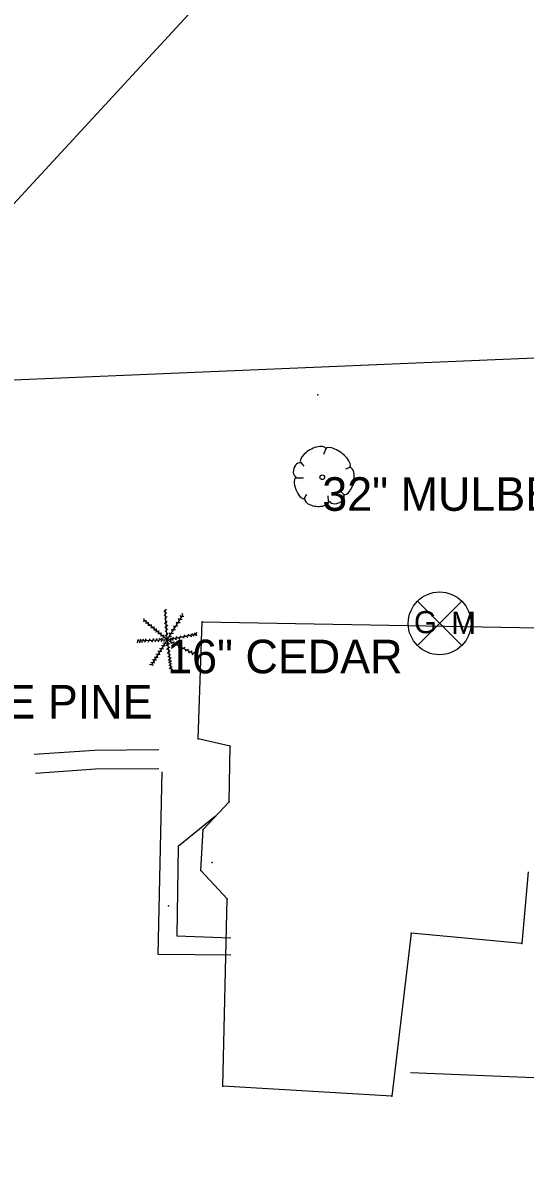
# Model space of a CAD drawing. Extents: x 1930288 to 1941089, y 588389 to 611475.
# Drawn here: x 1930694.7 to 1930769.5, y 598010.8 to 598182.1 of the extents above; entities that cross this region are included whole.
import ezdxf

# ---------------------------------------------------------------- set-up
doc = ezdxf.new("R2010")
doc.units = 0
for name, color, linetype in [('S_BUILDING', 7, 'Continuous'), ('S_DRIVEWAY', 7, 'Continuous'), ('S_GAS_UTILITIES', 7, 'Continuous'), ('S_MSC_PT_SYM', 7, 'Continuous'), ('S_SIDEWALK', 7, 'Continuous'), ('S_STR_PT_SYM', 7, 'Continuous'), ('S_TREE', 7, 'Continuous'), ('S_TREE_ANNOT', 7, 'Continuous'), ('S_UNDERGROUND_CABLE', 7, 'Continuous')]:
    doc.layers.add(name, color=color, linetype=linetype)

msp = doc.modelspace()

# ---------------------------------------------------------------- linework, layer by layer
at = {"layer": 'S_BUILDING'}
for p, q in [((1930720.81, 598075.51), (1930721.4, 598092.94)), ((1930721.4, 598092.94), (1930771.5, 598092.05)), ((1930725.6, 598074.42), (1930720.81, 598075.51)), ((1930725.42, 598066.11), (1930725.6, 598074.42)), ((1930721.59, 598061.99), (1930725.42, 598066.11)), ((1930721.23, 598055.87), (1930721.59, 598061.99)), ((1930725.15, 598051.69), (1930721.23, 598055.87)), ((1930769.97, 598055.71), (1930769.07, 598044.99)), ((1930724.49, 598023.76), (1930725.15, 598051.69)), ((1930752.57, 598046.55), (1930749.68, 598022.29)), ((1930769.07, 598044.99), (1930752.57, 598046.55)), ((1930749.68, 598022.29), (1930724.49, 598023.76))]:
    msp.add_line(p, q, dxfattribs=at)
at = {"layer": 'S_DRIVEWAY'}
msp.add_lwpolyline([(1930752.46, 598025.79), (1930772.06, 598025.01), (1930774.1, 598023.8), (1930774.87, 598021.62), (1930775.13, 598011.33), (1930788.72, 598010.83), (1930789.53, 598023.35), (1930791.28, 598024.6), (1930814.28, 598024.07), (1930827.31, 598023.8), (1930840.35, 598023.53), (1930845.84, 598023.33)], dxfattribs=at)
at = {"layer": 'S_GAS_UTILITIES'}
for p, q in [((1930763.56, 598231.34), (1930683.07, 598144.05)), ((1930753.49, 598089.39), (1930760.11, 598096.01)), ((1930753.49, 598096.01), (1930760.11, 598089.39))]:
    msp.add_line(p, q, dxfattribs=at)
msp.add_circle((1930756.8, 598092.7), 4.68, dxfattribs=at)
at = {"layer": 'S_MSC_PT_SYM'}
for points in [[(1930738.65, 598126.76), (1930738.65, 598126.81), (1930738.65, 598126.76), (1930738.6, 598126.76), (1930738.65, 598126.76), (1930738.65, 598126.71), (1930738.65, 598126.76), (1930738.7, 598126.76)], [(1930722.92, 598057.07), (1930722.92, 598057.12), (1930722.92, 598057.07), (1930722.86, 598057.07), (1930722.92, 598057.07), (1930722.92, 598057.02), (1930722.92, 598057.07), (1930722.97, 598057.07)], [(1930716.4, 598050.61), (1930716.4, 598050.66), (1930716.4, 598050.61), (1930716.35, 598050.61), (1930716.4, 598050.61), (1930716.4, 598050.56), (1930716.4, 598050.61), (1930716.45, 598050.61)]]:
    msp.add_lwpolyline(points, dxfattribs=at)
at = {"layer": 'S_SIDEWALK'}
for points in [[(1930696.38, 598073.19), (1930705.4, 598073.81), (1930714.96, 598073.9)], [(1930696.57, 598070.4), (1930705.51, 598071.01), (1930714.98, 598071.1)], [(1930725.69, 598043.3), (1930714.87, 598043.4), (1930715.16, 598056.98), (1930715.44, 598070.57)], [(1930723.42, 598063.97), (1930717.86, 598059.45), (1930717.66, 598046.16), (1930725.67, 598045.88)]]:
    msp.add_lwpolyline(points, dxfattribs=at)
at = {"layer": 'S_STR_PT_SYM'}
for points in [[(1930721.4, 598092.94), (1930721.4, 598092.99), (1930721.4, 598092.94), (1930721.35, 598092.94), (1930721.4, 598092.94), (1930721.4, 598092.89), (1930721.4, 598092.94), (1930721.45, 598092.94)], [(1930720.81, 598075.51), (1930720.81, 598075.56), (1930720.81, 598075.51), (1930720.76, 598075.51), (1930720.81, 598075.51), (1930720.81, 598075.46), (1930720.81, 598075.51), (1930720.86, 598075.51)], [(1930725.6, 598074.42), (1930725.6, 598074.47), (1930725.6, 598074.42), (1930725.55, 598074.42), (1930725.6, 598074.42), (1930725.6, 598074.37), (1930725.6, 598074.42), (1930725.65, 598074.42)], [(1930725.42, 598066.11), (1930725.42, 598066.16), (1930725.42, 598066.11), (1930725.37, 598066.11), (1930725.42, 598066.11), (1930725.42, 598066.06), (1930725.42, 598066.11), (1930725.47, 598066.11)], [(1930721.59, 598061.99), (1930721.59, 598062.04), (1930721.59, 598061.99), (1930721.54, 598061.99), (1930721.59, 598061.99), (1930721.59, 598061.94), (1930721.59, 598061.99), (1930721.64, 598061.99)], [(1930721.23, 598055.87), (1930721.23, 598055.92), (1930721.23, 598055.87), (1930721.18, 598055.87), (1930721.23, 598055.87), (1930721.23, 598055.82), (1930721.23, 598055.87), (1930721.28, 598055.87)], [(1930725.15, 598051.69), (1930725.15, 598051.74), (1930725.15, 598051.69), (1930725.1, 598051.69), (1930725.15, 598051.69), (1930725.15, 598051.64), (1930725.15, 598051.69), (1930725.2, 598051.69)], [(1930752.57, 598046.55), (1930752.57, 598046.6), (1930752.57, 598046.55), (1930752.52, 598046.55), (1930752.57, 598046.55), (1930752.57, 598046.5), (1930752.57, 598046.55), (1930752.62, 598046.55)], [(1930769.07, 598044.99), (1930769.07, 598045.04), (1930769.07, 598044.99), (1930769.02, 598044.99), (1930769.07, 598044.99), (1930769.07, 598044.94), (1930769.07, 598044.99), (1930769.12, 598044.99)], [(1930724.49, 598023.76), (1930724.49, 598023.81), (1930724.49, 598023.76), (1930724.44, 598023.76), (1930724.49, 598023.76), (1930724.49, 598023.71), (1930724.49, 598023.76), (1930724.54, 598023.76)], [(1930749.68, 598022.29), (1930749.68, 598022.34), (1930749.68, 598022.29), (1930749.63, 598022.29), (1930749.68, 598022.29), (1930749.68, 598022.24), (1930749.68, 598022.29), (1930749.73, 598022.29)]]:
    msp.add_lwpolyline(points, dxfattribs=at)
at = {"layer": 'S_TREE'}
for p, q in [((1930739.86, 598118.7), (1930739.48, 598117.85)), ((1930736.07, 598116.69), (1930736.57, 598116.11)), ((1930743.43, 598115.91), (1930742.77, 598115.64)), ((1930735.41, 598114.36), (1930736.53, 598114.36)), ((1930736.57, 598111.19), (1930737.03, 598111.88)), ((1930740.25, 598110.91), (1930740.17, 598111.69)), ((1930742.65, 598111.81), (1930742.19, 598112.23)), ((1930715.95, 598094.34), (1930715.72, 598094.54)), ((1930715.98, 598093.77), (1930715.76, 598093.97)), ((1930716.2, 598090.26), (1930715.93, 598094.69)), ((1930715.95, 598094.58), (1930716.13, 598094.82)), ((1930715.97, 598094.11), (1930716.16, 598094.34)), ((1930716.01, 598093.51), (1930716.2, 598093.74)), ((1930716.2, 598090.26), (1930718.55, 598093.94)), ((1930718.27, 598093.57), (1930718.19, 598093.85)), ((1930718.41, 598093.73), (1930718.71, 598093.77)), ((1930718.52, 598093.91), (1930718.43, 598094.19)), ((1930712.92, 598093), (1930712.62, 598092.96)), ((1930716.2, 598090.26), (1930712.74, 598093.17)), ((1930712.78, 598093.14), (1930712.78, 598093.44)), ((1930713.27, 598092.72), (1930712.97, 598092.7)), ((1930713.09, 598092.89), (1930713.09, 598093.19)), ((1930713.63, 598092.4), (1930713.33, 598092.37)), ((1930713.45, 598092.6), (1930713.45, 598092.9)), ((1930714.09, 598092.02), (1930713.79, 598092)), ((1930713.86, 598092.24), (1930713.86, 598092.54)), ((1930714.27, 598091.91), (1930714.27, 598092.21)), ((1930714.6, 598091.62), (1930714.6, 598091.92)), ((1930716.01, 598093.2), (1930715.79, 598093.4)), ((1930716.04, 598092.54), (1930715.81, 598092.74)), ((1930716.07, 598091.95), (1930715.85, 598092.14)), ((1930716.05, 598092.8), (1930716.23, 598093.03)), ((1930716.11, 598092.23), (1930716.3, 598092.46)), ((1930716.12, 598091.66), (1930716.31, 598091.89)), ((1930717.31, 598092.03), (1930717.22, 598092.32)), ((1930717.52, 598092.27), (1930717.82, 598092.31)), ((1930717.68, 598092.6), (1930717.59, 598092.88)), ((1930717.84, 598092.81), (1930718.14, 598092.85)), ((1930717.98, 598093.11), (1930717.89, 598093.4)), ((1930718.16, 598093.3), (1930718.46, 598093.34)), ((1930716.2, 598090.26), (1930711.75, 598090.04)), ((1930711.98, 598090.07), (1930711.82, 598090.31)), ((1930712.37, 598090.09), (1930712.2, 598090.34)), ((1930712.77, 598090.09), (1930712.6, 598090.34)), ((1930713.17, 598090.12), (1930713, 598090.37)), ((1930713.46, 598090.13), (1930713.32, 598089.86)), ((1930713.74, 598090.13), (1930713.57, 598090.38)), ((1930716.2, 598090.26), (1930713.82, 598086.48)), ((1930714.02, 598090.15), (1930713.88, 598089.88)), ((1930714.29, 598090.17), (1930714.13, 598090.42)), ((1930714.45, 598091.69), (1930714.15, 598091.67)), ((1930714.5, 598090.17), (1930714.37, 598089.9)), ((1930714.78, 598091.43), (1930714.49, 598091.41)), ((1930714.77, 598090.18), (1930714.6, 598090.43)), ((1930715.13, 598091.13), (1930714.83, 598091.11)), ((1930714.97, 598090.2), (1930714.84, 598089.93)), ((1930714.96, 598091.32), (1930714.96, 598091.62)), ((1930715.21, 598090.22), (1930715.04, 598090.47)), ((1930715.49, 598090.84), (1930715.19, 598090.81)), ((1930715.43, 598090.2), (1930715.3, 598089.94)), ((1930715.33, 598091.02), (1930715.33, 598091.32)), ((1930715.55, 598090.26), (1930715.38, 598090.51)), ((1930715.86, 598090.54), (1930715.56, 598090.52)), ((1930715.82, 598090.22), (1930715.68, 598089.95)), ((1930715.69, 598090.7), (1930715.69, 598091)), ((1930716.11, 598091.38), (1930715.89, 598091.58)), ((1930716.13, 598090.76), (1930715.9, 598090.96)), ((1930716.15, 598090.99), (1930716.34, 598091.22)), ((1930716.2, 598090.26), (1930720.62, 598091.12)), ((1930716.2, 598090.26), (1930720.12, 598088.21)), ((1930716.2, 598090.26), (1930716.73, 598085.88)), ((1930716.53, 598090.07), (1930716.8, 598090.21)), ((1930716.55, 598090.75), (1930716.85, 598090.79)), ((1930716.65, 598091.01), (1930716.56, 598091.3)), ((1930716.58, 598090.34), (1930716.78, 598090.56)), ((1930716.82, 598090.37), (1930717.08, 598090.21)), ((1930716.84, 598091.21), (1930717.13, 598091.25)), ((1930717.01, 598091.54), (1930716.92, 598091.83)), ((1930716.98, 598090.4), (1930717.18, 598090.62)), ((1930717.17, 598091.75), (1930717.47, 598091.8)), ((1930717.34, 598090.45), (1930717.59, 598090.29)), ((1930717.51, 598090.5), (1930717.71, 598090.72)), ((1930717.86, 598090.57), (1930718.11, 598090.4)), ((1930718.08, 598090.63), (1930718.28, 598090.85)), ((1930718.46, 598090.69), (1930718.72, 598090.53)), ((1930718.71, 598090.77), (1930718.91, 598090.99)), ((1930719.04, 598090.8), (1930719.3, 598090.64)), ((1930719.3, 598090.86), (1930719.5, 598091.09)), ((1930719.55, 598090.91), (1930719.81, 598090.75)), ((1930719.79, 598090.97), (1930719.99, 598091.19)), ((1930719.98, 598091), (1930720.23, 598090.84)), ((1930720.23, 598091.06), (1930720.43, 598091.28)), ((1930720.38, 598091.06), (1930720.64, 598090.9)), ((1930720.46, 598091.11), (1930720.66, 598091.33)), ((1930711.84, 598090.04), (1930711.7, 598089.77)), ((1930712.18, 598090.07), (1930712.05, 598089.8)), ((1930712.53, 598090.09), (1930712.39, 598089.82)), ((1930712.95, 598090.1), (1930712.81, 598089.83)), ((1930715.11, 598088.53), (1930714.81, 598088.49)), ((1930715.36, 598088.95), (1930715.06, 598088.91)), ((1930715.25, 598088.75), (1930715.32, 598088.46)), ((1930715.64, 598089.39), (1930715.34, 598089.36)), ((1930715.51, 598089.16), (1930715.58, 598088.87)), ((1930715.87, 598089.76), (1930715.58, 598089.72)), ((1930715.78, 598089.6), (1930715.86, 598089.31)), ((1930716, 598089.93), (1930716.07, 598089.64)), ((1930716.27, 598089.58), (1930716.07, 598089.35)), ((1930716.33, 598089), (1930716.13, 598088.77)), ((1930716.41, 598088.44), (1930716.22, 598088.21)), ((1930716.28, 598089.83), (1930716.54, 598089.67)), ((1930716.32, 598089.27), (1930716.58, 598089.12)), ((1930716.4, 598088.71), (1930716.66, 598088.55)), ((1930716.71, 598089.98), (1930716.78, 598089.69)), ((1930717.01, 598089.85), (1930717.28, 598089.99)), ((1930717.29, 598089.67), (1930717.36, 598089.38)), ((1930717.56, 598089.55), (1930717.83, 598089.69)), ((1930717.83, 598089.4), (1930717.9, 598089.11)), ((1930718.12, 598089.26), (1930718.38, 598089.4)), ((1930718.35, 598089.13), (1930718.42, 598088.83)), ((1930718.6, 598089), (1930718.87, 598089.14)), ((1930718.89, 598088.83), (1930718.96, 598088.54)), ((1930719.14, 598088.73), (1930719.4, 598088.87)), ((1930719.4, 598088.57), (1930719.47, 598088.28)), ((1930719.69, 598088.46), (1930719.95, 598088.6)), ((1930714.06, 598086.87), (1930713.76, 598086.83)), ((1930713.98, 598086.73), (1930714.05, 598086.44)), ((1930714.31, 598087.28), (1930714.01, 598087.25)), ((1930714.2, 598087.07), (1930714.28, 598086.78)), ((1930714.55, 598087.66), (1930714.25, 598087.62)), ((1930714.46, 598087.47), (1930714.54, 598087.18)), ((1930714.84, 598088.11), (1930714.54, 598088.07)), ((1930714.71, 598087.86), (1930714.78, 598087.57)), ((1930714.99, 598088.32), (1930715.07, 598088.03)), ((1930716.48, 598087.87), (1930716.29, 598087.64)), ((1930716.55, 598087.41), (1930716.35, 598087.18)), ((1930716.59, 598087.03), (1930716.39, 598086.8)), ((1930716.47, 598088.16), (1930716.72, 598088)), ((1930716.54, 598087.65), (1930716.8, 598087.49)), ((1930716.57, 598087.22), (1930716.83, 598087.06)), ((1930716.62, 598086.81), (1930716.87, 598086.65)), ((1930719.89, 598088.32), (1930719.96, 598088.03)), ((1930720.08, 598088.25), (1930720.35, 598088.39)), ((1930713.86, 598086.57), (1930713.56, 598086.53)), ((1930716.65, 598086.59), (1930716.45, 598086.36)), ((1930716.69, 598086.17), (1930716.49, 598085.94)), ((1930716.68, 598086.35), (1930716.94, 598086.19)), ((1930716.72, 598086), (1930716.98, 598085.85))]:
    msp.add_line(p, q, dxfattribs=at)
msp.add_circle((1930739.31, 598114.46), 0.341, dxfattribs=at)
for centre, major_axis, ratio, start_param, end_param in [((1930737.97, 598117.66), (1.86, 1.08), 0.471018, 0, 3.141593), ((1930741.62, 598117.34), (-1.81, 1.36), 0.405113, 3.141593, 6.283186), ((1930735.73, 598115.55), (0.31, 1.03), 0.646762, 0, 3.141593), ((1930742.98, 598113.93), (0.46, 2.04), 0.482994, 3.141593, 6.283185), ((1930736.04, 598112.89), (-0.61, 1.6), 0.420543, 6.283185, 9.424777), ((1930738.5, 598111.11), (-1.83, 0.19), 0.529943, 0, 3.141593), ((1930741.46, 598111.41), (1.09, 0.46), 0.711534, 3.141592, 6.283185)]:
    msp.add_ellipse(centre, major_axis=major_axis, ratio=ratio, start_param=start_param, end_param=end_param, dxfattribs=at)
at = {"layer": 'S_UNDERGROUND_CABLE'}
msp.add_line((1930623.81, 598126.06), (1930834.39, 598134.93), dxfattribs=at)

# ---------------------------------------------------------------- texts
at = {"layer": 'S_GAS_UTILITIES'}
for s, p in [('G', (1930752.98, 598091.23)), ('M', (1930758.54, 598091.13))]:
    msp.add_text(s, height=3.3, rotation=360, dxfattribs=at).set_placement(p)
at = {"layer": 'S_TREE_ANNOT'}
for s, p in [('32" MULBERRY', (1930739.31, 598109.46)), ('16" CEDAR', (1930716.2, 598085.26)), ('20" PIME 20" PNE PINE', (1930641.29, 598078.52))]:
    msp.add_text(s, height=5, dxfattribs=at).set_placement(p)

doc.saveas('drawing.dxf')
